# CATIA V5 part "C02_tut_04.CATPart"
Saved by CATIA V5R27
Part number: Part1
Bounding box of the stored display mesh (mm): x 0 to 0, y -50 to 100.45, z -30 to 49.999
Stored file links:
  E:\_Deepak\2017_Deepak\CATIA\Resources\Tutorial Files\Tutorials\c02_catia_v5_6r2016_tut\C02_tut_04.CATPart
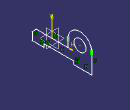
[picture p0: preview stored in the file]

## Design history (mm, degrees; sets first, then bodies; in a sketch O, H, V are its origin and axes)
Body1 (main body)
  Sketch1 on yz-plane, origin (0, 0, 0), H (0, 1, 0), V (0, 0, 1)
    line L1 (-50, -30) -> (-20, -30)
    line L2 (-20, -30) -> (-20, -22)
    line L3 (-20, -22) -> (55, -22)
    line L4 (55, -22) -> (55, -30)
    line L5 (55, -30) -> (55.45, -30)
    line L6 (55.45, -30) -> (100.45, -30)
    line L7 (100.45, -30) -> (100.45, 20)
    arc A1 centre (70.45, 20) radius 30 from (100.45, 20) to (40.45, 20) ccw
    line L8 (40.45, 20) -> (40.45, 0)
    line L9 (40.45, 0) -> (-40, 0)
    line L10 (-40, 0) -> (-50, -10)
    line L11 (-50, -10) -> (-50, -30)
    circle A2 centre (70.45, 20) radius 15
    horizontal: L1 H, L3 H, L5 H, L6 H, L9 H
    vertical: L2 V, L4 V, L7 V, L11 V
    tangency: A1 L7, L8 A1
